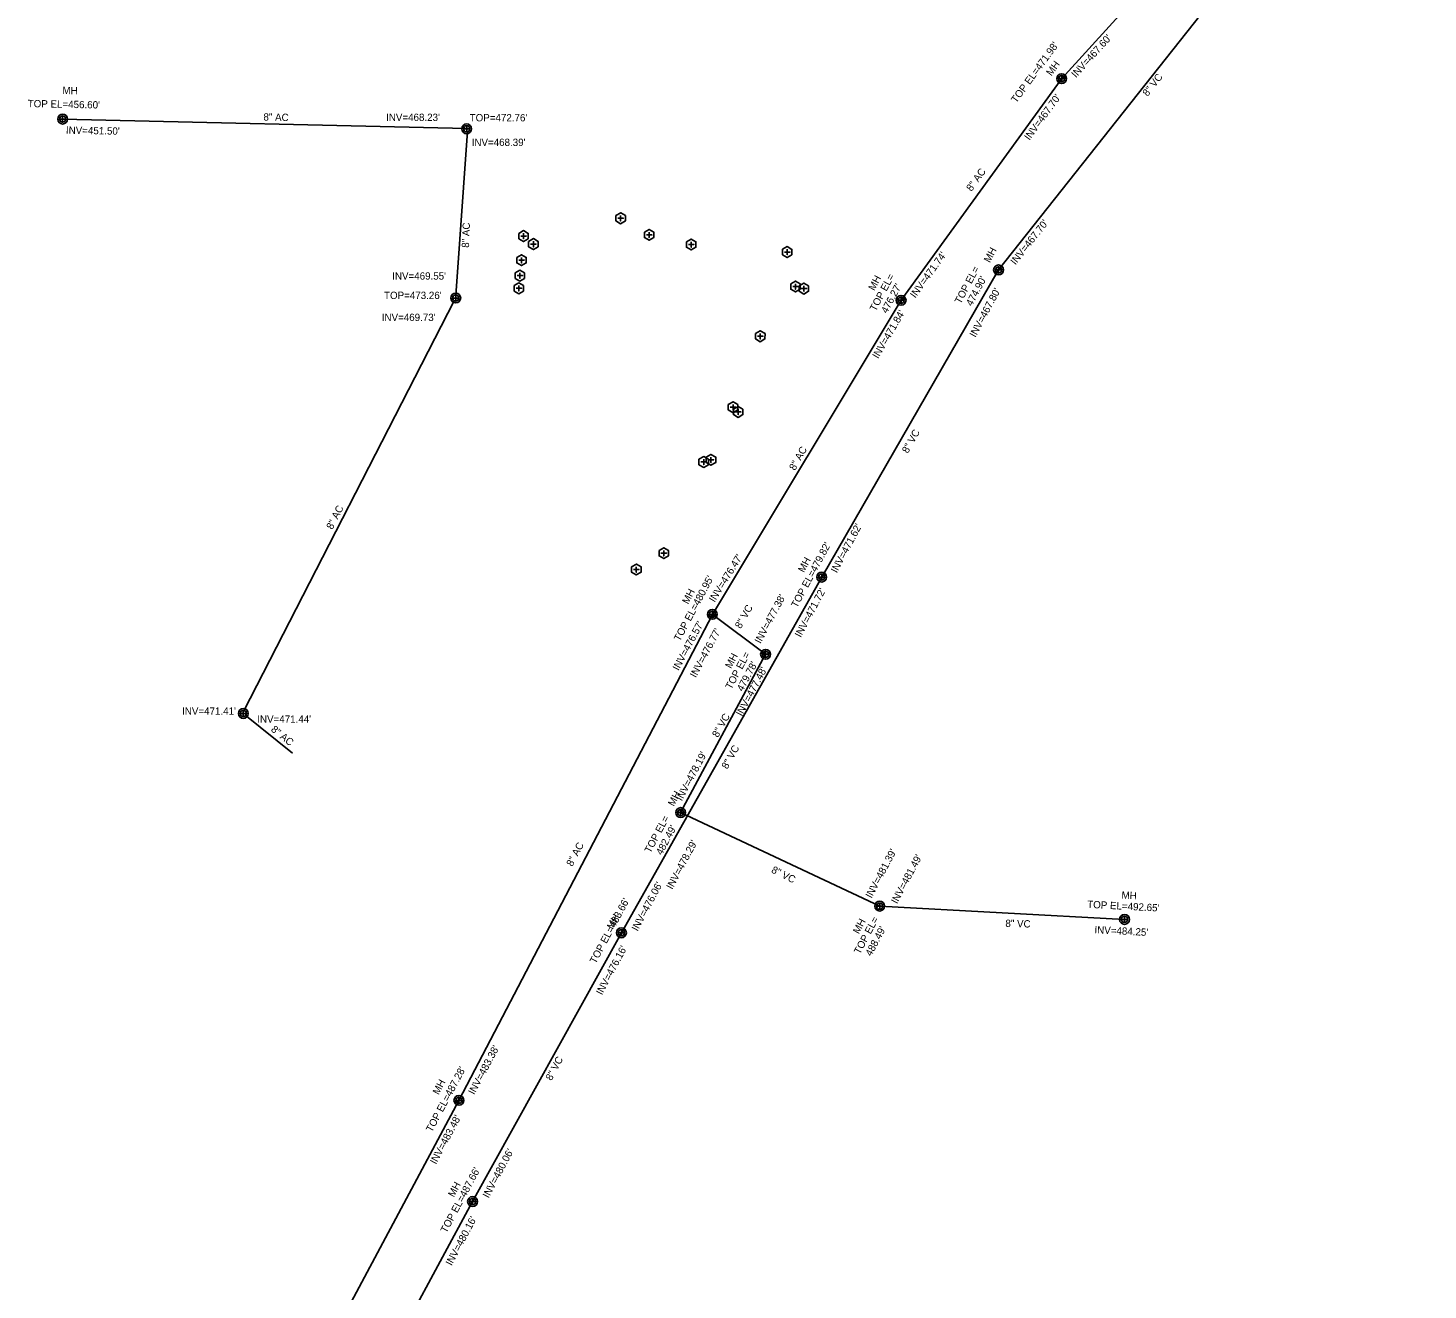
# Model space of a CAD drawing. Extents: x 1975698 to 1978521, y 778259 to 782969.
# Drawn here: x 1975866 to 1976632, y 778910 to 779600 of the extents above; entities that cross this region are included whole.
import ezdxf

# ---------------------------------------------------------------- set-up
doc = ezdxf.new("R2010")
doc.units = 0
for name, color, linetype in [('Exist Utilities Sanitary Sewer UG Line Invert Elevation', 7, 'Continuous'), ('Old_Level_11', 7, 'Continuous'), ('Prop Conc Curb 8in x 18in', 7, 'Continuous'), ('Prop Horizontal Alignment', 7, 'Continuous'), ('Prop Horizontal Alignment Station Label', 7, 'Continuous'), ('Prop Lane Arrow CELL', 7, 'Continuous'), ('Prop WCC CELL', 7, 'Continuous')]:
    doc.layers.add(name, color=color, linetype=linetype)

# ---------------------------------------------------------------- blocks, each defined once
blk = doc.blocks.new('EXIST UTILITIES SANITARY SEWER MANHOLE')
at = {"layer": 'Prop Horizontal Alignment'}
blk.add_lwpolyline([(0, 0.034), (0, -0.034), (0, 0), (0.034, 0), (-0.034, 0)], dxfattribs=at)
for radius in [0.0539, 0.0342]:
    blk.add_circle((0, 0), radius, dxfattribs=at)

msp = doc.modelspace()

# ---------------------------------------------------------------- linework, layer by layer
at = {"layer": 'Prop Conc Curb 8in x 18in'}
for p, q in [((1976189.92, 779496.17), (1976189.92, 779496.17)), ((1976136.76, 779486.42), (1976136.76, 779486.42)), ((1976205.49, 779487.09), (1976205.49, 779487.09)), ((1976142.14, 779482.04), (1976142.14, 779482.04)), ((1976228.5, 779481.81), (1976228.5, 779481.81)), ((1976135.67, 779473.24), (1976135.67, 779473.24)), ((1976281.06, 779477.67), (1976281.06, 779477.67)), ((1976134.76, 779464.76), (1976134.76, 779464.76)), ((1976134.2, 779457.85), (1976134.2, 779457.85)), ((1976285.56, 779458.82), (1976285.56, 779458.82)), ((1976290.19, 779457.69), (1976290.19, 779457.69)), ((1976266.31, 779431.59), (1976266.31, 779431.59)), ((1976251.39, 779392.76), (1976251.39, 779392.76)), ((1976254.22, 779390.2), (1976254.22, 779390.2)), ((1976239.34, 779363.99), (1976239.34, 779363.99)), ((1976235.34, 779362.79), (1976235.34, 779362.79)), ((1976213.5, 779312.91), (1976213.5, 779312.91)), ((1976198.49, 779303.95), (1976198.49, 779303.95))]:
    msp.add_line(p, q, dxfattribs=at)
for points in [[(1976187.34, 779497.66), (1976187.34, 779494.68), (1976189.92, 779493.19), (1976192.5, 779494.67), (1976192.51, 779497.65), (1976189.93, 779499.14)], [(1976134.18, 779487.91), (1976134.18, 779484.93), (1976136.75, 779483.44), (1976139.34, 779484.92), (1976139.34, 779487.9), (1976136.77, 779489.4)], [(1976202.91, 779488.58), (1976202.91, 779485.6), (1976205.48, 779484.11), (1976208.07, 779485.59), (1976208.07, 779488.57), (1976205.49, 779490.07)], [(1976139.57, 779483.53), (1976139.56, 779480.55), (1976142.14, 779479.06), (1976144.72, 779480.54), (1976144.73, 779483.52), (1976142.15, 779485.02)], [(1976225.92, 779483.31), (1976225.91, 779480.33), (1976228.49, 779478.83), (1976231.07, 779480.32), (1976231.08, 779483.3), (1976228.5, 779484.79)], [(1976278.48, 779479.17), (1976278.48, 779476.19), (1976281.06, 779474.69), (1976283.64, 779476.18), (1976283.65, 779479.16), (1976281.07, 779480.65)], [(1976133.09, 779474.73), (1976133.09, 779471.75), (1976135.66, 779470.26), (1976138.25, 779471.74), (1976138.25, 779474.72), (1976135.68, 779476.22)], [(1976132.18, 779466.25), (1976132.17, 779463.27), (1976134.75, 779461.78), (1976137.33, 779463.26), (1976137.34, 779466.24), (1976134.76, 779467.74)], [(1976131.62, 779459.34), (1976131.61, 779456.36), (1976134.19, 779454.87), (1976136.77, 779456.35), (1976136.78, 779459.33), (1976134.2, 779460.83)], [(1976282.98, 779460.32), (1976282.97, 779457.34), (1976285.55, 779455.84), (1976288.13, 779457.33), (1976288.14, 779460.31), (1976285.56, 779461.8)], [(1976287.61, 779459.19), (1976287.6, 779456.21), (1976290.18, 779454.71), (1976292.76, 779456.2), (1976292.77, 779459.18), (1976290.19, 779460.67)], [(1976263.74, 779433.09), (1976263.73, 779430.11), (1976266.31, 779428.61), (1976268.89, 779430.1), (1976268.9, 779433.08), (1976266.32, 779434.57)], [(1976248.81, 779394.26), (1976248.81, 779391.28), (1976251.39, 779389.78), (1976253.97, 779391.27), (1976253.98, 779394.25), (1976251.4, 779395.74)], [(1976251.64, 779391.69), (1976251.63, 779388.71), (1976254.21, 779387.22), (1976256.79, 779388.7), (1976256.8, 779391.68), (1976254.22, 779393.18)], [(1976232.77, 779364.29), (1976232.76, 779361.31), (1976235.34, 779359.81), (1976237.92, 779361.3), (1976237.93, 779364.28), (1976235.35, 779365.77)], [(1976236.76, 779365.48), (1976236.75, 779362.5), (1976239.33, 779361.01), (1976241.92, 779362.49), (1976241.92, 779365.47), (1976239.34, 779366.97)], [(1976210.92, 779314.4), (1976210.91, 779311.42), (1976213.49, 779309.93), (1976216.08, 779311.41), (1976216.08, 779314.39), (1976213.5, 779315.89)], [(1976195.91, 779305.45), (1976195.91, 779302.47), (1976198.49, 779300.97), (1976201.07, 779302.46), (1976201.08, 779305.44), (1976198.5, 779306.93)]]:
    msp.add_lwpolyline(points, close=True, dxfattribs=at)
for points in [[(1976189.92, 779497.68), (1976189.92, 779494.65), (1976189.92, 779496.17), (1976191.44, 779496.17), (1976188.41, 779496.17)], [(1976136.76, 779487.93), (1976136.76, 779484.91), (1976136.76, 779486.42), (1976138.27, 779486.42), (1976135.25, 779486.42)], [(1976205.49, 779488.6), (1976205.49, 779485.57), (1976205.49, 779487.09), (1976207, 779487.09), (1976203.98, 779487.09)], [(1976142.14, 779483.55), (1976142.14, 779480.53), (1976142.14, 779482.04), (1976143.66, 779482.04), (1976140.63, 779482.04)], [(1976228.5, 779483.32), (1976228.5, 779480.3), (1976228.5, 779481.81), (1976230.01, 779481.81), (1976226.98, 779481.81)], [(1976281.06, 779479.19), (1976281.06, 779476.16), (1976281.06, 779477.67), (1976282.58, 779477.67), (1976279.55, 779477.67)], [(1976135.67, 779474.75), (1976135.67, 779471.73), (1976135.67, 779473.24), (1976137.18, 779473.24), (1976134.16, 779473.24)], [(1976134.76, 779466.27), (1976134.76, 779463.24), (1976134.76, 779464.76), (1976136.27, 779464.76), (1976133.24, 779464.76)], [(1976134.2, 779459.36), (1976134.2, 779456.33), (1976134.2, 779457.85), (1976135.71, 779457.85), (1976132.68, 779457.85)], [(1976285.56, 779460.34), (1976285.56, 779457.31), (1976285.56, 779458.82), (1976287.07, 779458.82), (1976284.04, 779458.82)], [(1976290.19, 779459.21), (1976290.19, 779456.18), (1976290.19, 779457.69), (1976291.7, 779457.69), (1976288.67, 779457.69)], [(1976266.31, 779433.1), (1976266.31, 779430.08), (1976266.31, 779431.59), (1976267.83, 779431.59), (1976264.8, 779431.59)], [(1976251.39, 779394.27), (1976251.39, 779391.25), (1976251.39, 779392.76), (1976252.9, 779392.76), (1976249.88, 779392.76)], [(1976254.22, 779391.71), (1976254.22, 779388.68), (1976254.22, 779390.2), (1976255.73, 779390.2), (1976252.7, 779390.2)], [(1976235.34, 779364.3), (1976235.34, 779361.28), (1976235.34, 779362.79), (1976236.86, 779362.79), (1976233.83, 779362.79)], [(1976239.34, 779365.5), (1976239.34, 779362.48), (1976239.34, 779363.99), (1976240.85, 779363.99), (1976237.82, 779363.99)], [(1976213.5, 779314.42), (1976213.5, 779311.4), (1976213.5, 779312.91), (1976215.01, 779312.91), (1976211.98, 779312.91)], [(1976198.49, 779305.46), (1976198.49, 779302.44), (1976198.49, 779303.95), (1976200, 779303.95), (1976196.98, 779303.95)]]:
    msp.add_lwpolyline(points, dxfattribs=at)
at = {"layer": 'Prop Horizontal Alignment'}
for points in [[(1976105.67, 779546.8), (1976105.67, 779543.37), (1976105.67, 779545.09), (1976107.38, 779545.09), (1976103.96, 779545.09)], [(1976099.7, 779454.21), (1976099.7, 779450.79), (1976099.7, 779452.5), (1976101.41, 779452.5), (1976097.98, 779452.5)], [(1975983.43, 779226.89), (1975983.43, 779223.47), (1975983.43, 779225.18), (1975985.14, 779225.18), (1975981.72, 779225.18)]]:
    msp.add_lwpolyline(points, dxfattribs=at)
for centre, radius in [((1976105.67, 779545.09), 2.69), ((1976105.67, 779545.09), 1.71), ((1976099.7, 779452.5), 2.69), ((1976099.7, 779452.5), 1.71), ((1975983.43, 779225.18), 2.69), ((1975983.43, 779225.18), 1.71)]:
    msp.add_circle(centre, radius, dxfattribs=at)
at = {"layer": 'Prop Horizontal Alignment Station Label'}
for p, q in [((1976431.23, 779572.58), (1976631.67, 779793.27)), ((1976396.69, 779467.91), (1976530.08, 779636.44)), ((1976343.36, 779451.28), (1976431.23, 779572.58)), ((1976105.71, 779545.36), (1975884.59, 779550.43)), ((1976099.67, 779453.88), (1976106.04, 779543.91)), ((1976299.93, 779299.8), (1976396.69, 779467.91)), ((1975983.52, 779226.28), (1976098.94, 779451.36)), ((1976240.1, 779279.41), (1976343.36, 779451.28)), ((1976190.33, 779105.16), (1976299.93, 779299.8)), ((1976101.41, 779013.48), (1976240.1, 779279.41)), ((1976240.1, 779279.41), (1976269.22, 779257.58)), ((1976269.22, 779257.58), (1976222.73, 779170.96)), ((1975984.34, 779224.49), (1976010.4, 779203.43)), ((1976222.73, 779170.96), (1976331.66, 779119.76)), ((1976331.66, 779119.76), (1976465.62, 779112.48)), ((1976108.88, 778958.11), (1976190.33, 779105.16)), ((1975960.52, 778749.94), (1976101.41, 779013.48)), ((1975956.48, 778675.34), (1976108.88, 778958.11))]:
    msp.add_line(p, q, dxfattribs=at)

# ---------------------------------------------------------------- block references
at = {"layer": 'Prop Horizontal Alignment', "xscale": 50, "yscale": 50}
for p in [(1976431.23, 779572.58), (1975884.59, 779550.43), (1976396.69, 779467.91), (1976343.36, 779451.28), (1976299.93, 779299.8), (1976240.1, 779279.41), (1976269.22, 779257.58), (1976222.73, 779170.96), (1976331.66, 779119.76), (1976465.62, 779112.48), (1976190.33, 779105.16), (1976101.41, 779013.48), (1976108.88, 778958.11)]:
    msp.add_blockref('EXIST UTILITIES SANITARY SEWER MANHOLE', p, dxfattribs=at)

# ---------------------------------------------------------------- texts
at = {"layer": 'Exist Utilities Sanitary Sewer UG Line Invert Elevation'}
for s, p in [("INV=468.23'", (1976061.58, 779549.41)), ("INV=468.39'", (1976108.41, 779535.71)), ("INV=469.55'", (1976064.93, 779462.59)), ("INV=469.73'", (1976059.22, 779439.94)), ("INV=471.41'", (1975949.95, 779224.49)), ("INV=471.44'", (1975991.09, 779220.08))]:
    msp.add_text(s, height=4, rotation=0.00002, dxfattribs=at).set_placement(p)
at = {"layer": 'Old_Level_11'}
for s, rotation, p in [('8" VC', 51.63927, (1976478.2, 779562.58)), ('8" AC', 54.0803, (1976381.88, 779510.56)), ('8" VC', 60.61616, (1976347.05, 779367.22)), ('8" AC', 60.61616, (1976285.3, 779357.82)), ('8" AC', 62.84972, (1976032.16, 779325.52)), ('8" VC', 60.61616, (1976255.62, 779271.26)), ('8" AC', 321.06069, (1975998.23, 779215.84)), ('8" VC', 60.61616, (1976243.14, 779211.73)), ('8" VC', 60.61616, (1976248.27, 779194.42)), ('8" AC', 61.87066, (1976163.44, 779141.18)), ('8" VC', 333.52425, (1976272.02, 779138.32)), ('8" VC', 358.49654, (1976400.39, 779108.39)), ('8" VC', 61.87066, (1976152.08, 779023.94))]:
    msp.add_text(s, height=4, rotation=rotation, dxfattribs=at).set_placement(p)
at = {"layer": 'Prop Lane Arrow CELL'}
for s, p in [("TOP=472.76'", (1976107.31, 779549.2)), ("TOP=473.26'", (1976060.45, 779451.98))]:
    msp.add_text(s, height=4, rotation=0.00002, dxfattribs=at).set_placement(p)
at = {"layer": 'Prop WCC CELL'}
for s, rotation, p in [("INV=467.60'", 47.75165, (1976439.05, 779572.76)), ("TOP EL=471.98'", 53.82679, (1976406.41, 779558.9)), ('MH', 53.82679, (1976425.6, 779573.73)), ('MH', 358.83301, (1975884.44, 779564.15)), ("INV=467.70'", 53.82679, (1976413.61, 779538.49)), ("TOP EL=456.60'", 358.83301, (1975865.44, 779556.99)), ('8" AC', 358.68733, (1975994.42, 779549.64)), ("INV=451.50'", 358.83301, (1975886.36, 779542.45)), ("INV=467.70'", 51.63927, (1976405.94, 779470.35)), ('8" AC', 87.76006, (1976106.93, 779479.96)), ('MH', 61.91412, (1976391.88, 779471.54)), ("INV=471.74'", 54.0803, (1976351.14, 779452.19)), ('MH', 61.91412, (1976328.7, 779456.24)), ('TOP EL=', 61.91412, (1976329.47, 779444.91)), ('TOP EL=', 61.91412, (1976375.94, 779448.97)), ("474.90'", 61.91412, (1976382.1, 779447.76)), ("476.27'", 61.91412, (1976335.66, 779443.76)), ("INV=467.80'", 61.91412, (1976384.07, 779430.67)), ("INV=471.84'", 59.63108, (1976330.79, 779419.03)), ("INV=471.62'", 61.91412, (1976308.2, 779301.75)), ("TOP EL=479.82'", 61.91412, (1976286.46, 779282.66)), ("INV=476.47'", 58.09759, (1976241.29, 779285.7)), ('MH', 61.91412, (1976290.22, 779301.99)), ("TOP EL=480.95'", 61.91412, (1976222.3, 779264.34)), ('MH', 61.91412, (1976226.79, 779284.7)), ("INV=477.38'", 61.91412, (1976266.48, 779263.06)), ("INV=471.72'", 61.91412, (1976288.46, 779266.47)), ("INV=476.57'", 61.91412, (1976221.59, 779248.3)), ("INV=476.77'", 61.91412, (1976231.08, 779244.43)), ('MH', 61.91412, (1976250.33, 779249.46)), ('TOP EL=', 61.91412, (1976250.49, 779238)), ("INV=477.48'", 61.91412, (1976256.33, 779223.34)), ("479.78'", 61.91412, (1976256.72, 779236.92)), ("INV=478.19'", 61.91412, (1976223.4, 779176.96)), ('MH', 61.91412, (1976219.02, 779174.06)), ('TOP EL=', 61.91412, (1976206.24, 779148.44)), ("482.49'", 61.91412, (1976212.47, 779147.36)), ("INV=478.29'", 61.91412, (1976218.18, 779128.59)), ("INV=481.39'", 61.91412, (1976327.15, 779123.75)), ("INV=481.49'", 61.91412, (1976341.14, 779120.69)), ("INV=476.06'", 61.91412, (1976199.16, 779105.73)), ('MH', 357.00965, (1976463.89, 779123.91)), ("TOP EL=483.66'", 61.91412, (1976176.26, 779087.93)), ("TOP EL=492.65'", 357.00965, (1976445.11, 779118.83)), ('MH', 61.91412, (1976185.65, 779106.75)), ('MH', 61.91412, (1976320.23, 779104.24)), ('TOP EL=', 61.91412, (1976320.82, 779093.1)), ("488.49'", 61.91412, (1976327.05, 779092.03)), ("INV=484.25'", 357.00965, (1976449.09, 779104.95)), ("INV=476.16'", 61.91412, (1976179.7, 779070.8)), ("INV=483.38'", 61.91412, (1976109.8, 779016.26)), ("TOP EL=487.28'", 61.91412, (1976086.65, 778995.72)), ('MH', 61.91412, (1976090.29, 779016.25)), ("INV=483.48'", 61.91412, (1976088.88, 778978.15)), ("INV=480.06'", 61.91412, (1976117.64, 778959.69)), ("TOP EL=487.66'", 61.91412, (1976094.61, 778940.56)), ('MH', 61.91412, (1976098.69, 778960.17)), ("INV=480.16'", 61.91412, (1976097.43, 778922.68))]:
    msp.add_text(s, height=4, rotation=rotation, dxfattribs=at).set_placement(p)

doc.saveas('drawing.dxf')
